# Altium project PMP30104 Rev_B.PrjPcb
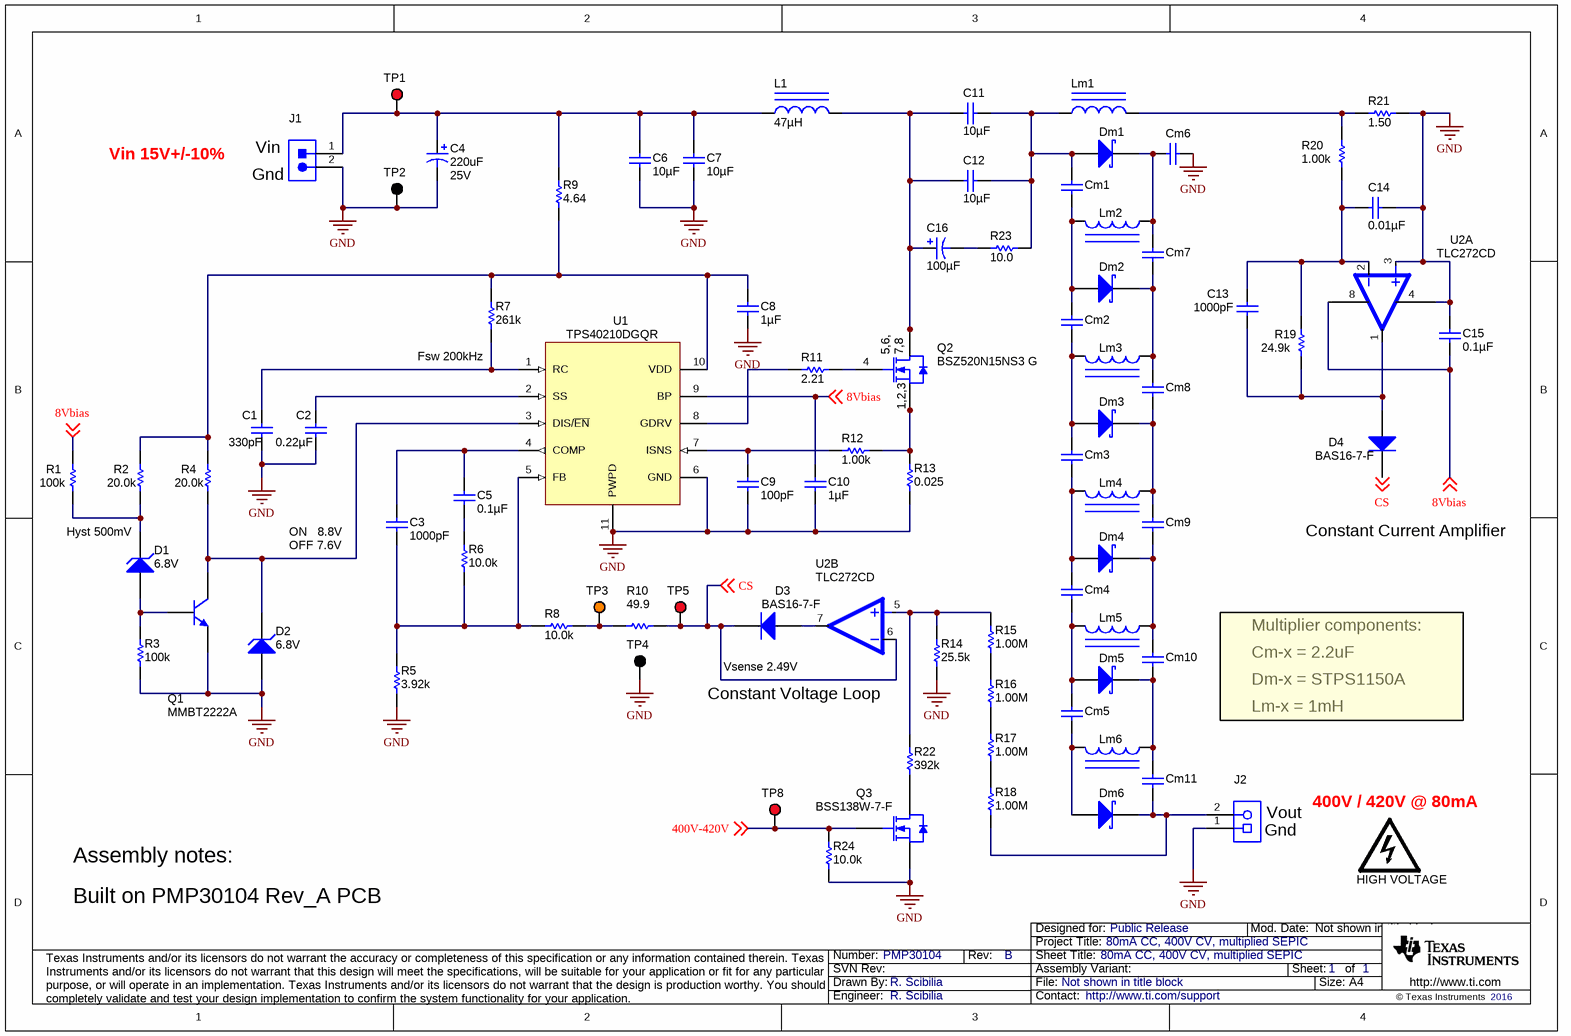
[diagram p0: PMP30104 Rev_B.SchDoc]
CopyrightYear: 2016; PRJ_Customer: Public Release; PRJ_Engineer: R. Scibilia; PRJ_Number: PMP30104; PRJ_Title: 80mA CC, 400V CV, multiplied SEPIC; SCH_Rev: B; TechSupport: http://www.ti.com/support
1 sheet, 82 parts. Net scope: global (net labels, ports and power ports of the same name join across sheets).
Board file: PMP30104 Rev_A PCB.PcbDoc

## Sheet PMP30104 Rev_B.SchDoc: 80mA CC, 400V CV, multiplied SEPIC
size A4; Date: Not shown in title block; ApprovedBy: Not shown in title block; CheckedBy: Not shown in title block; Author: Not shown in title block; CompanyName: Not shown in title block; DrawnBy: R. Scibilia; Engineer: Not shown in title block; Organization: Not shown in title block; Address1: Not shown in title block; Address2: Not shown in title block; Address3: Not shown in title block; Address4: Not shown in title block; DocumentNumber: 1; Revision: Use project parameter SCH_Rev; SheetNumber: 1; SheetTotal: 1; PageSetup: Record=PageOptions¦CenterHorizontal=True¦CenterVertical=True¦PrintScale=0.70¦XCorrection=1.00¦YCorrection=1.00¦PrintKind=0¦BorderSize=5000000¦LeftOffset=0¦BottomOffset=0¦Orientation=2¦PaperLength=1000¦PaperWidth=1000¦Scale=100¦PaperSource=15¦PrintQuality=600¦MediaType=1¦DitherType=10¦PaperKind=A4¦PrintScaleMode=1

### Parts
C1  ValueDisplayed: 330pF  [0603]  (hidden comment: GRM188R71H331KA01D)
C2  ValueDisplayed: 0.22µF  [0603]  (hidden comment: GRM188R71E224KA88D)
C3  ValueDisplayed: 1000pF  [0603]  (hidden comment: GRM188R71H102KA01D)
C4  value 220uF  Value2: 25V  [SM_RADIAL_G]  (hidden comment: EEE-FC1E221P)
C5  ValueDisplayed: 0.1µF  [0603]  (hidden comment: GRM188R71H104KA93D)
C6  ValueDisplayed: 10µF  [0805_HV]  (hidden comment: C2012X5R1E106K125AB)
C7  ValueDisplayed: 10µF  [0805_HV]  (hidden comment: C2012X5R1E106K125AB)
C8  ValueDisplayed: 1µF  [0805_HV]  (hidden comment: GRM21BR71H105KA12L)
C9  ValueDisplayed: 100pF  [0603]  (hidden comment: 06033C101KAT2A)
C10  ValueDisplayed: 1µF  [0603]  (hidden comment: GRM188R71E105KA12D)
C11  ValueDisplayed: 10µF  [1206_180]  (hidden comment: C3216X5R1H106K160AB)
C12  ValueDisplayed: 10µF  [1206_180]  (hidden comment: C3216X5R1H106K160AB)
C13  ValueDisplayed: 1000pF  [0603]  (hidden comment: GRM188R71H102KA01D)
C14  ValueDisplayed: 0.01µF  [0603]  (hidden comment: GRM188R71H103KA01D)
C15  ValueDisplayed: 0.1µF  [0603]  (hidden comment: GCM188R71H104KA57D)
C16  ValueDisplayed: 100µF  [SM_RADIAL_D8]  (hidden comment: EEE-FK1E101XP)
Cm1  GRM31CR72A225KA73K  [1206_190]  (value not drawn)
Cm2  GRM31CR72A225KA73K  [1206_190]  (value not drawn)
Cm3  GRM31CR72A225KA73K  [1206_190]  (value not drawn)
Cm4  GRM31CR72A225KA73K  [1206_190]  (value not drawn)
Cm5  GRM31CR72A225KA73K  [1206_190]  (value not drawn)
Cm6  GRM31CR72A225KA73K  [1206_190]  (value not drawn)
Cm7  GRM31CR72A225KA73K  [1206_190]  (value not drawn)
Cm8  GRM31CR72A225KA73K  [1206_190]  (value not drawn)
Cm9  GRM31CR72A225KA73K  [1206_190]  (value not drawn)
Cm10  GRM31CR72A225KA73K  [1206_190]  (value not drawn)
Cm11  GRM31CR72A225KA73K  [1206_190]  (value not drawn)
D1  value 6.8V  [sod-323]  (hidden comment: MMSZ5235BS-7-F)
D2  value 6.8V  [sod-323]  (hidden comment: MMSZ5235BS-7-F)
D3  BAS16-7-F  [SOT-23]
D4  BAS16-7-F  [SOT-23]
Dm1  STPS1150A  [SMA]  (value not drawn)
Dm2  STPS1150A  [SMA]  (value not drawn)
Dm3  STPS1150A  [SMA]  (value not drawn)
Dm4  STPS1150A  [SMA]  (value not drawn)
Dm5  STPS1150A  [SMA]  (value not drawn)
Dm6  STPS1150A  [SMA]  (value not drawn)
HIGH_VOLTAGE  DANGER HIGH VOLTAGE  [IEC_HighVoltage_Large]  (value not drawn)  (no BOM)
J1  ED555/2DS  [TERM_BLK_ED555-2DS]  (value not drawn)
J2  691 101 710 002  [Wurth_691101710002]  (value not drawn)
L1  ValueDisplayed: 47µH  [WE-PD_1210]  (hidden comment: 7447709470)
Lm1  74477730  [WE-PD_7345]  (value not drawn)
Lm2  74477730  [WE-PD_7345]  (value not drawn)
Lm3  74477730  [WE-PD_7345]  (value not drawn)
Lm4  74477730  [WE-PD_7345]  (value not drawn)
Lm5  74477730  [WE-PD_7345]  (value not drawn)
Lm6  74477730  [WE-PD_7345]  (value not drawn)
Q1  MMBT2222A  [SOT-23]
Q2  BSZ520N15NS3 G  [PG-TSDSON-8]
Q3  BSS138W-7-F  [SOT-323]
R1  value 100k  [0603]  (hidden comment: CRCW0603100KFKEA)
R2  value 20.0k  [0603]  (hidden comment: CRCW060320K0FKEA)
R3  value 100k  [0603]  (hidden comment: CRCW0603100KFKEA)
R4  value 20.0k  [0603]  (hidden comment: CRCW060320K0FKEA)
R5  value 3.92k  [0603]  (hidden comment: CRCW06033K92FKEA)
R6  value 10.0k  [0603]  (hidden comment: CRCW060310K0FKEA)
R7  ValueDisplayed: 261k  [0603]  (hidden comment: RC0603FR-07261KL)
R8  value 10.0k  [0603]  (hidden comment: CRCW060310K0FKEA)
R9  value 4.64  [0603]  (hidden comment: CRCW06034R64FKEA)
R10  value 49.9  [0603]  (hidden comment: CRCW060349R9FKEA)
R11  ValueDisplayed: 2.21  [0603]  (hidden comment: RC0603FR-072R21L)
R12  value 1.00k  [0603]  (hidden comment: CRCW06031K00FKEA)
R13  value 0.025  [2010M]  (hidden comment: CSRN2010FK25L0)
R14  ValueDisplayed: 25.5k  [0603]  (hidden comment: RC0603FR-0725K5L)
R15  ValueDisplayed: 1.00M  [1206]  (hidden comment: RC1206FR-071ML)
R16  ValueDisplayed: 1.00M  [1206]  (hidden comment: RC1206FR-071ML)
R17  ValueDisplayed: 1.00M  [1206]  (hidden comment: RC1206FR-071ML)
R18  ValueDisplayed: 1.00M  [1206]  (hidden comment: RC1206FR-071ML)
R19  ValueDisplayed: 24.9k  [0603]  (hidden comment: RC0603FR-0724K9L)
R20  ValueDisplayed: 1.00k  [0603]  (hidden comment: CRCW06031K00FKEA)
R21  ValueDisplayed: 1.50  [0805_HV]  (hidden comment: RC0805FR-071R5L)
R22  ValueDisplayed: 392k  [0603]  (hidden comment: RC0603FR-07392KL)
R23  ValueDisplayed: 10.0  [0805_HV]  (hidden comment: RC0805FR-0710RL)
R24  value 10.0k  [0603]  (hidden comment: CRCW060310K0FKEA)
TP1  5000  [Keystone5000]  (value not drawn)
TP2  5001  [Keystone5001]  (value not drawn)
TP3  5003  [Keystone5003]  (value not drawn)
TP4  5001  [Keystone5001]  (value not drawn)
TP5  5000  [Keystone5000]  (value not drawn)
TP8  5000  [Keystone5000]  (value not drawn)
U1  TPS40210DGQR  [DGQ0010D_N]
U2  TLC272CD  [D0008A_N]  (parts A,B of 2)

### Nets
GND: C1.2 C2.2 C4.2(-) C6.2 C7.2 C8.2 C9.2 C10.2 C14.1 C15.1 Cm6.1 D2.2(A) J1.2 J2.1 Q1.2(E) Q3.2(S) R3.1 R5.1 R13.1 R14.1 R21.2 R24.2 TP2.1 TP4.1 U1.6(GND) U1.11(PWPD) U2.3(IN+) U2.4(GND)
8Vbias: C10.1 C15.2 R1.2 U1.9(BP) U2.8(VCC) ; off-sheet 8Vbias
400V-420V: Q3.1(G) R24.1 TP8.1 ; off-sheet 400V-420V
CS: D3.3(K) D4.3(K) R10.2 TP5.1 U2.6(IN-) ; off-sheet CS
NetC1_1: C1.1 R7.1 U1.1(RC)
NetC2_1: C2.1 U1.2(SS)
NetC3_1: C3.1 C5.1 U1.4(COMP)
NetC3_2: C3.2 R5.2 R6.2 R8.1 U1.5(FB)
NetC4_1: C4.1(+) C6.1 C7.1 J1.1 L1.1 R9.2 TP1.1
NetC5_2: C5.2 R6.1
NetC8_1: C8.1 R2.2 R4.2 R7.2 R9.1 U1.10(VDD)
NetC9_1: C9.1 R12.1 U1.7(ISNS)
NetC11_1: C11.1 C12.1 Cm1.1 Dm1.2(A) Lm1.1 R23.2
NetC11_2: C11.2 C12.2 C16.1(+) L1.2 Q2.5(D) Q2.6(D) Q2.7(D) Q2.8(D) Q2.9(D)
NetC13_1: C13.1 C14.2 R19.1 R20.2 U2.2(IN-)
NetC13_2: C13.2 D4.1(A) R19.2 U2.1(OUT1)
NetC16_2: C16.2(-) R23.1
NetCm1_2: Cm1.2 Cm2.1 Dm2.2(A) Lm2.1
NetCm2_2: Cm2.2 Cm3.1 Dm3.2(A) Lm3.1
NetCm3_2: Cm3.2 Cm4.1 Dm4.2(A) Lm4.1
NetCm4_2: Cm4.2 Cm5.1 Dm5.2(A) Lm5.1
NetCm5_2: Cm5.2 Dm6.2(A) Lm6.1
NetCm6_2: Cm6.2 Cm7.1 Dm1.1(K) Lm2.2
NetCm7_2: Cm7.2 Cm8.1 Dm2.1(K) Lm3.2
NetCm8_2: Cm8.2 Cm9.1 Dm3.1(K) Lm4.2
NetCm9_2: Cm9.2 Cm10.1 Dm4.1(K) Lm5.2
NetCm10_2: Cm10.2 Cm11.1 Dm5.1(K) Lm6.2
NetCm11_2: Cm11.2 Dm6.1(K) J2.2 R18.1
NetD1_1: D1.1(K) R1.1 R2.1
NetD1_2: D1.2(A) Q1.1(B) R3.2
NetD2_1: D2.1(K) Q1.3(C) R4.1 U1.3(DIS/~{EN})
NetD3_1: D3.1(A) U2.7(OUT)
NetLm1_2: Lm1.2 R20.1 R21.1
NetQ2_1: Q2.1(S) Q2.2(S) Q2.3(S) R12.2 R13.2
NetQ2_4: Q2.4(G) R11.2
NetQ3_3: Q3.3(D) R22.1
NetR8_2: R8.2 R10.1 TP3.1
NetR11_1: R11.1 U1.8(GDRV)
NetR14_2: R14.2 R15.2 R22.2 U2.5(IN+)
NetR15_1: R15.1 R16.2
NetR16_1: R16.1 R17.2
NetR17_1: R17.1 R18.2

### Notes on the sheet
- Vin 15V+/-10%
- (near J1) Vin
- (near J1) Gnd
- (near R7) Fsw 200kHz
- Hyst 500mV
- (near C3) ON   8.8V
- OFF 7.6V
- Constant Current Amplifier
- Multiplier components:
- Cm-x = 2.2uF
- Constant Voltage Loop
- Vsense 2.49V
- Dm-x = STPS1150A
- Lm-x = 1mH
- Assembly notes:
- (near J2) Vout
- (near J2) Gnd
- (near HIGH_VOLTAGE) 400V / 420V @ 80mA
- Built on PMP30104 Rev_A PCB

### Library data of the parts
C1 = GRM188R71H331KA01D: CAP, CERM, 330pF, 50V, +/-10%, X7R, 0603; Manufacturer: MuRata; Polarized: N; CompType: Capacitor; U/M: EA; Cap_F: 0.00000000033; Tolerance_%: 10; Value1: Unknown; VDC_V: 50; TaMin_C: -55; TaMax_C: 125
C2 = GRM188R71E224KA88D: CAP, CERM, 0.22uF, 25V, +/-10%, X7R, 0603; Manufacturer: MuRata; Polarized: N; CompType: Capacitor; U/M: EA; Cap_F: 0.00000022; Tolerance_%: 10; Value1: Unknown; VDC_V: 25; TaMin_C: -55; TaMax_C: 125
C3 C13 = GRM188R71H102KA01D: CAP, CERM, 1000pF, 50V, +/-10%, X7R, 0603; Manufacturer: MuRata; Polarized: N; CompType: Capacitor; U/M: EA; Cap_F: 0.000000001; Tolerance_%: 10; Value1: Unknown; VDC_V: 50; TaMin_C: -55; TaMax_C: 125
C4 = EEE-FC1E221P: CAP, AL, 220 µF, 25 V, +/- 20%, 0.15 ohm, SMD; Manufacturer: Panasonic; Polarized: Y; CompType: Capacitor; ValueDisplayed: 220µF; U/M: EA; Cap_F: 0.00022; Tolerance_%: 20; VDC_V: 25; ESR_ohm: 0.15; IRMS_A: 0.67; TaMin_C: -40; TaMax_C: 105; Cap_Case: G; AEC Category: Q200
C5 = GRM188R71H104KA93D: CAP, CERM, 0.1 µF, 50 V, +/- 10%, X7R, 0603; Manufacturer: MuRata; Polarized: N; CompType: Capacitor; Value: 0.1uF; U/M: EA; Cap_F: 0.0000001; Tolerance_%: 10; Value1: Unknown; VDC_V: 50; Value2: 50V; TaMin_C: -55; TaMax_C: 125
C6 C7 = C2012X5R1E106K125AB: CAP, CERM, 10 µF, 25 V, +/- 10%, X5R, 0805; Manufacturer: TDK; Polarized: N; CompType: Capacitor; Value: 10uF; U/M: EA; Cap_F: 0.00001; Tolerance_%: 10; Value1: Unknown; VDC_V: 25; Value2: 25V; TaMin_C: -55; TaMax_C: 85; Cap_Case: 0805; SizeArea_mm2: 2.5; SizeAreaWB_mm2: 6.75; SizeX_mm: 2; SizeY_mm: 1.25; SizeZ_mm: 1.45; AEC Category: Q200
C8 = GRM21BR71H105KA12L: CAP, CERM, 1uF, 50V, +/-10%, X7R, 0805; Manufacturer: MuRata; Polarized: N; CompType: Capacitor; U/M: EA; Cap_F: 0.000001; Tolerance_%: 10; Value1: Unknown; VDC_V: 50; TaMin_C: -55; TaMax_C: 125; Cap_Case: 0805
C9 = 06033C101KAT2A: CAP, CERM, 100pF, 25V, +/-10%, X7R, 0603; Manufacturer: AVX; Polarized: N; CompType: Capacitor; U/M: EA; Cap_F: 0.0000000001; Tolerance_%: 10; Value1: Unknown; VDC_V: 25; TaMin_C: -55; TaMax_C: 125
C10 = GRM188R71E105KA12D: CAP, CERM, 1uF, 25V, +/-10%, X7R, 0603; Manufacturer: MuRata; Polarized: N; CompType: Capacitor; U/M: EA; Cap_F: 0.000001; Tolerance_%: 10; Value1: Unknown; VDC_V: 25; TaMin_C: -55; TaMax_C: 125
C11 C12 = C3216X5R1H106K160AB: CAP, CERM, 10 µF, 50 V, +/- 10%, X5R, 1206; Manufacturer: TDK; Polarized: N; CompType: Capacitor; Value: 10uF; U/M: EA; Cap_F: 0.00001; Tolerance_%: 10; ESR_ohm: 0.002229; Value1: 0.002229 ohm; VDC_V: 50; Value2: 50V; IRMS_A: 4.85932; TaMin_C: -55; TaMax_C: 85; SizeArea_mm2: 5.12; SizeAreaWB_mm2: 10.92; SizeX_mm: 3.2; SizeY_mm: 1.6; SizeZ_mm: 1.8; AEC Category: Q200
C14 = GRM188R71H103KA01D: CAP, CERM, 0.01uF, 50V, +/-10%, X7R, 0603; Manufacturer: MuRata; Polarized: N; CompType: Capacitor; U/M: EA; Cap_F: 0.00000001; Tolerance_%: 10; Value1: Unknown; VDC_V: 50; TaMin_C: -55; TaMax_C: 125
C15 = GCM188R71H104KA57D: CAP, CERM, 0.1uF, 50V, +/-10%, X7R, 0603; Manufacturer: MuRata; Polarized: N; CompType: Capacitor; U/M: EA; Cap_F: 0.0000001; Tolerance_%: 10; ESR_Ohm: 0.02; Value1: 0.02 ohm; VDC_V: 50; IRMS_A: 1.84; TaMin_C: -55; TaMax_C: 125
C16 = EEE-FK1E101XP: CAP, AL, 100 µF, 25 V, +/- 20%, 0.34 ohm, SMD; Manufacturer: Panasonic; Polarized: Y; CompType: Capacitor; Value: 100uF; U/M: EA; Cap_F: 0.0001; Tolerance_%: 20; VDC_V: 25; Value2: 25V; ESR_ohm: 0.34; IRMS_A: 0.28; TaMin_C: -55; TaMax_C: 105; Cap_Case: D8; AEC Category: Q200
Cm1-Cm11 = GRM31CR72A225KA73L: CAP, CERM, 2.2 µF, 100 V, +/- 10%, X7R, 1206_190; Manufacturer: MuRata; Polarized: N; CompType: Capacitor; Value: 2.2uF; ValueDisplayed: 2.2µF; U/M: EA; Cap_F: 0.0000022; Tolerance_%: 10; Value1: Unknown; VDC_V: 100; Value2: 100V; TaMin_C: -55; TaMax_C: 125; Cap_Case: 1206; SizeArea_mm2: 5.12; SizeAreaWB_mm2: 10.92; SizeX_mm: 3.2; SizeY_mm: 1.6; SizeZ_mm: 1.9; AEC Category: Q200
D1 D2 = MMSZ5235BS-7-F: Diode, Zener, 6.8V, 200mW, SOD-323; Manufacturer: Diodes Inc.; SymbolCreator: a0412235; U/M: EA; Power_W: 0.2; Vz_V: 6.8; Value1: 0.2W; RJA_CperW: 350
D3 D4 = BAS16-7-F: Diode, Ultrafast, 75V, 0.3A, SOT-23; Manufacturer: Diodes Inc.; U/M: EA; Vf_V: 1.125; Value2: 1.125V; Io_A: 0.3; Vr_V: 75
Dm1-Dm6 = STPS1150A: Diode, Schottky, 150 V, 1 A, SMA; Manufacturer: STMicroelectronics; U/M: EA; Vf_V: 0.78; Value1: 1A; Value2: 0.78V; Io_A: 1; Vr_V: 150; TJmax_C: 175; RJC_CperW: 30; SizeAreaWB_mm2: 37.3428; SizeArea_mm2: 16.3228; SizeX_mm: 5.59; SizeY_mm: 2.92; SizeZ_mm: 2.87; AEC Category: Q101; AEC Qualified: N
HIGH_VOLTAGE = IEC_HighVoltage: IEC 61010-1 High Voltage Warning; SymbolCreator: a0412235
J1 = ED555/2DS: Terminal Block, 6A, 3.5mm Pitch, 2-Pos, TH; Manufacturer: On-Shore Technology; SymbolCreator: a0412235; CompType: Connector; U/M: EA
J2 = 691 101 710 002: Terminal Block, 5 mm, 2x1, Tin, TH; Manufacturer: Wurth Elektronik; SymbolCreator: a0412235
L1 = 7447709470: Inductor, Shielded Drum Core, Ferrite, 47 µH, 3.8 A, 0.04593 ohm, SMD; Manufacturer: Wurth Elektronik; Value: 47uH; Ind_H: 47.0E-6; Imax_A: 3.8; Irms: 3.8A @ 40C rise; Isat: 4.5A @ 10% inductance drop; Value2: 3.8A; AEC Category: Q200
Lm1-Lm6 = 74477730: Inductor, Shielded Drum Core, Metal Composite, 1 mH, 0.2 A, 3.27 ohm, SMD; Manufacturer: Wurth Elektronik; Value: 1mH; Ind_H: 1.0E-3; Imax_A: 0.2; Irms: 0.2A @ 40C rise; Isat: 0.25A @ 10% inductance drop; DCR_ohm: 3.27; Value2: 0.2A; AEC Category: Q200
Q1 = MMBT2222A, Fairchild Semiconductor: Transistor, NPN, 40V, 0.15A, SOT-23; CompType: BJT; PNP: 0; NPN: 1; Vceo_V: 40; Vcesat1_V: 0.3; IcRated_A: 0.15; HfeMax: 300; TaMin_C: -55; TaMax_C: 150; U/M: EA
Q2 = BSZ520N15NS3 G: MOSFET, N-CH, 150 V, 21 A, PG-TSDSON-8; Manufacturer: Infineon Technologies; Alternate Manufacturer: None; U/M: EA; ChType: N; VdsMax_V: 150; Value1: ? ohm; Value2: 8.7 nC; QgTyp_nC: 8.7; Vgs_V: 20; IdsMax_A: 21; SizeAreaWB_mm2: 19.36; SizeArea_mm2: 11.56; SizeX_mm: 3.4; SizeZ_mm: 1.1; AEC Category: Q101
Q3 = BSS138W-7-F: MOSFET, N-CH, 50 V, 0.2 A, SOT-323; Manufacturer: Diodes Inc.; Alternate Manufacturer: None; U/M: EA; ChType: N; VdsMax_V: 50; Value1: 3.5 ohm; Rdson45_ohm: 3.5; Value2: ? nC; Vgs_V: 1.5; IdsMax_A: 0.2; SizeAreaWB_mm2: 10.24; SizeArea_mm2: 4.84; SizeX_mm: 2.2; SizeZ_mm: 1.1; AEC Category: Q101
R1 R3 = CRCW0603100KFKEA: RES, 100k ohm, 1%, 0.1W, 0603; Manufacturer: Vishay-Dale; CompType: Resistor; Res_ohm: 100000; Tolerance_%: 1; Power_W: 0.1; VDC_V: 75; TempCo: 100 ppm/C; EIA_Code: E96; U/M: EA
R2 R4 = CRCW060320K0FKEA: RES, 20.0k ohm, 1%, 0.1W, 0603; Manufacturer: Vishay-Dale; CompType: Resistor; Res_ohm: 20000; Value_Code: 20k0; Tolerance_%: 1; Power_W: 0.1; VDC_V: 75; TempCo: 100 ppm/C; EIA_Code: E96; U/M: EA
R5 = CRCW06033K92FKEA: RES, 3.92k ohm, 1%, 0.1W, 0603; Manufacturer: Vishay-Dale; CompType: Resistor; Res_ohm: 3920; Value_Code: 3k92; Tolerance_%: 1; Power_W: 0.1; VDC_V: 75; TempCo: 100 ppm/C; EIA_Code: E96; U/M: EA
R6 R8 R24 = CRCW060310K0FKEA: RES, 10.0k ohm, 1%, 0.1W, 0603; Manufacturer: Vishay-Dale; CompType: Resistor; Res_ohm: 10000; Value_Code: 10k0; Tolerance_%: 1; Power_W: 0.1; VDC_V: 75; TempCo: 100 ppm/C; EIA_Code: E96; U/M: EA
R7 = RC0603FR-07261KL: RES, 261 k, 1%, 0.1 W, 0603; Manufacturer: Yageo America; CompType: Resistor; Value: 261k; Res_ohm: 261000; Tolerance_%: 1; Power_W: 0.1; Value2: 0.1W; VDC_V: 150; TempCo: 200 ppm/C; SizeArea_mm2: 1.28; SizeX_mm: 1.6; SizeY_mm: 0.8; EIA_Code: E96; U/M: EA; AEC Category: Q200
R9 = CRCW06034R64FKEA: RES, 4.64 ohm, 1%, 0.1W, 0603; Manufacturer: Vishay-Dale; CompType: Resistor; Value_Code: 4R64; Tolerance_%: 1; Power_W: 0.1; VDC_V: 75; TempCo: 100 ppm/C; EIA_Code: E96; U/M: EA
R10 = CRCW060349R9FKEA: RES, 49.9 ohm, 1%, 0.1W, 0603; Manufacturer: Vishay-Dale; CompType: Resistor; Value_Code: 49R9; Tolerance_%: 1; Power_W: 0.1; VDC_V: 75; TempCo: 100 ppm/C; EIA_Code: E96; U/M: EA
R11 = RC0603FR-072R21L: RES, 2.21, 1%, 0.1 W, 0603; Manufacturer: Yageo America; CompType: Resistor; Value: 2.21; Value_Code: 2R21; Tolerance_%: 1; Power_W: 0.1; Value2: 0.1W; VDC_V: 150; TempCo: 200 ppm/C; SizeArea_mm2: 1.28; SizeX_mm: 1.6; SizeY_mm: 0.8; EIA_Code: E96; U/M: EA; AEC Category: Q200
R12 = CRCW06031K00FKEA: RES, 1.00k ohm, 1%, 0.1W, 0603; Manufacturer: Vishay-Dale; CompType: Resistor; Res_ohm: 1000; Value_Code: 1k00; Tolerance_%: 1; Power_W: 0.1; VDC_V: 75; TempCo: 100 ppm/C; EIA_Code: E96; U/M: EA
R13 = CSRN2010FK25L0: RES, 0.025 ohm, 1%, 1W, 2010; Manufacturer: Stackpole Electronics Inc; CompType: Resistor; Value_Code: R025; Tolerance_%: 1; TempCo: 250 ppm/C; EIA_Code: E96; U/M: EA
R14 = RC0603FR-0725K5L: RES, 25.5 k, 1%, 0.1 W, 0603; Manufacturer: Yageo America; CompType: Resistor; Value: 25.5k; Res_ohm: 25500; Value_Code: 25k5; Tolerance_%: 1; Power_W: 0.1; Value2: 0.1W; VDC_V: 150; TempCo: 200 ppm/C; SizeArea_mm2: 1.28; SizeX_mm: 1.6; SizeY_mm: 0.8; EIA_Code: E96; U/M: EA; AEC Category: Q200
R15-R18 = RC1206FR-071ML: RES, 1.00 M, 1%, 0.25 W, 1206; Manufacturer: Yageo America; CompType: Resistor; Value: 1.00Meg; Res_ohm: 1000000; Value_Code: 1M00; Tolerance_%: 1; Power_W: 0.25; Value2: 0.25W; VDC_V: 200; TempCo: 100 ppm/C; SizeArea_mm2: 5.12; SizeX_mm: 3.2; SizeY_mm: 1.6; SizeZ_mm: 1.35; EIA_Code: E96; U/M: EA; AEC Category: Q200
R19 = RC0603FR-0724K9L: RES, 24.9 k, 1%, 0.1 W, 0603; Manufacturer: Yageo America; CompType: Resistor; Value: 24.9k; Res_ohm: 24900; Value_Code: 24k9; Tolerance_%: 1; Power_W: 0.1; Value2: 0.1W; VDC_V: 150; TempCo: 200 ppm/C; SizeArea_mm2: 1.28; SizeX_mm: 1.6; SizeY_mm: 0.8; EIA_Code: E96; U/M: EA; AEC Category: Q200
R20 = CRCW06031K00FKEA: RES, 1.00 k, 1%, 0.1 W, 0603; Manufacturer: Vishay-Dale; CompType: Resistor; Value: 1.00k; Res_ohm: 1000; Value_Code: 1k00; Tolerance_%: 1; Power_W: 0.1; Value2: 0.1W; VDC_V: 75; TempCo: 100 ppm/C; EIA_Code: E96; U/M: EA
R21 = RC0805FR-071R5L: RES, 1.50, 1%, 0.125 W, 0805; Manufacturer: Yageo America; CompType: Resistor; Value: 1.50; Res_ohm: 1.5; Value_Code: 1R50; Tolerance_%: 1; Power_W: 0.125; Value2: 0.125W; VDC_V: 150; TempCo: 200 ppm/C; SizeArea_mm2: 2.5; SizeX_mm: 2; SizeY_mm: 1.25; SizeZ_mm: 1.45; EIA_Code: E96; U/M: EA; AEC Category: Q200
R22 = RC0603FR-07392KL: RES, 392 k, 1%, 0.1 W, 0603; Manufacturer: Yageo America; CompType: Resistor; Value: 392k; Res_ohm: 392000; Tolerance_%: 1; Power_W: 0.1; Value2: 0.1W; VDC_V: 150; TempCo: 200 ppm/C; SizeArea_mm2: 1.28; SizeX_mm: 1.6; SizeY_mm: 0.8; EIA_Code: E96; U/M: EA; AEC Category: Q200
R23 = RC0805FR-0710RL: RES, 10.0, 1%, 0.125 W, 0805; Manufacturer: Yageo America; CompType: Resistor; Value: 10.0; Res_ohm: 10; Value_Code: 10R0; Tolerance_%: 1; Power_W: 0.125; Value2: 0.125W; VDC_V: 150; TempCo: 200 ppm/C; SizeArea_mm2: 2.5; SizeX_mm: 2; SizeY_mm: 1.25; SizeZ_mm: 1.45; EIA_Code: E96; U/M: EA; AEC Category: Q200
TP1 TP5 TP8 = 5000: Test Point, Miniature, Red, TH; Manufacturer: Keystone; CompType: Test Point Loop; U/M: EA
TP2 TP4 = 5001: Test Point, Miniature, Black, TH; Manufacturer: Keystone; CompType: Test Point Loop; U/M: EA
TP3 = 5003: Test Point, Miniature, Orange, TH; Manufacturer: Keystone; CompType: Test Point Loop; U/M: EA
U1 = TPS40210DGQR: 4.5-V TO 52-V INPUT CURRENT MODE BOOST CONTROLLER, DGQ0010D; Alternate Manufacturer: Texas Instruments; SymbolCreator: a0412235; CompType: IC; U/M: EA
U2 = TLC272CD: IC, Precision Dual Operational Amplifiers; Manufacturer: Texas Instruments; Alternate Manufacturer: None; Area: 75900

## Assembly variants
001: all parts fitted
